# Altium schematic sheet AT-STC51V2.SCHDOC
size 300 x 200 mm
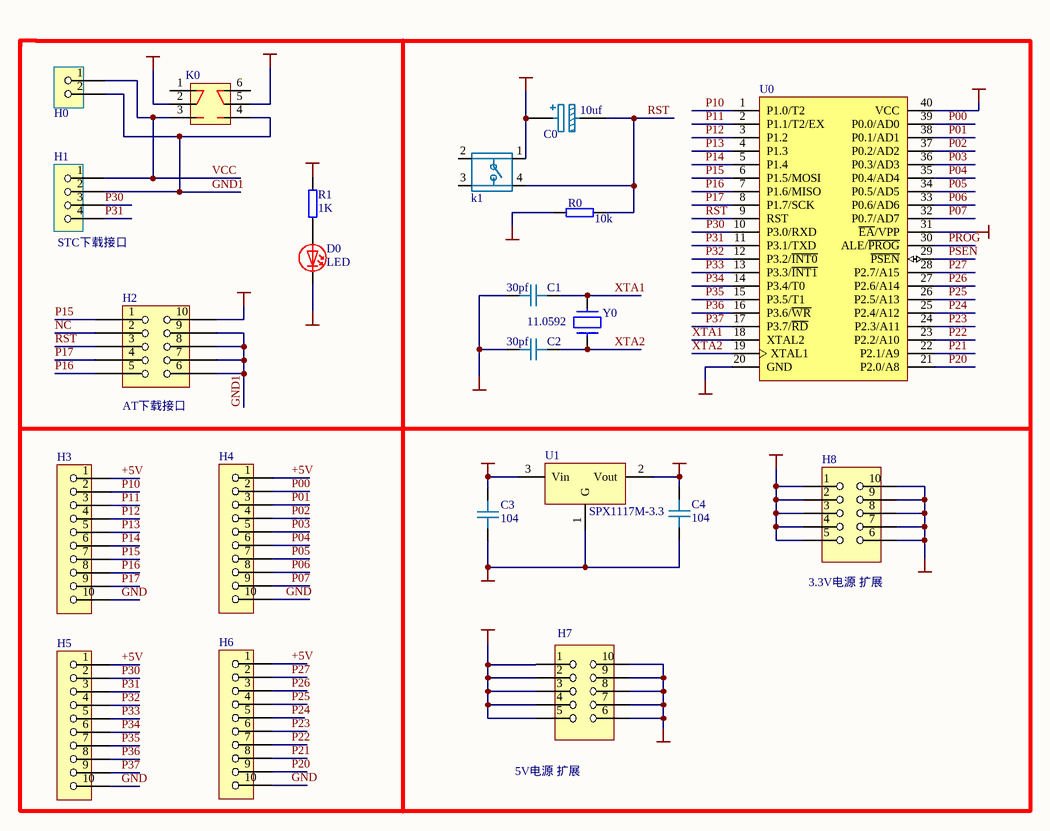
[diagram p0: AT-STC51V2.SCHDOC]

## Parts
C0  10uf  [Capacitor]
C1  30pf  [0805]
C2  30pf  [0805]
C3  104  [0805]
C4  104  [0805]
D0  LED  [LED-3]
H0  DIS2  [DIS2]  (value not drawn)
H1  DIS4  [dis4]  (value not drawn)
H2  PIN10  [DIS5*2-1]  (value not drawn)
H3  DIS10  [DIS10]  (value not drawn)
H4  DIS10  [DIS10]  (value not drawn)
H5  DIS10  [DIS10]  (value not drawn)
H6  DIS10  [DIS10]  (value not drawn)
H7  DIS5*2  [DIS5*2]  (value not drawn)
H8  DIS5*2  [DIS5*2]  (value not drawn)
K0  KEY  [KEY2]  (value not drawn)
k1  BUTTON  [BUTTON]  (value not drawn)
R0  10k  [resistor-0.4]
R1  1K  [resistor-0.4]
U0  AT89S52  [at89s51B]  (value not drawn)
U1  SPX1117M-3.3  [SPX1117M-3.3]
Y0  11.0592  [xtal_1]

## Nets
+3.3V: C4.2 H8.1 H8.2 H8.3 H8.4 H8.5 U1.2(Vout)
+5V: C0.1 C3.2 H3.1 H4.1 H5.1 H6.1 H7.1 H7.2 H7.3 H7.4 H7.5 K0.2 k1.1 R1.2 U0.31(~{EA}/VPP) U0.40(VCC) U1.3(Vin)
GND: C1.1 C2.1 C3.1 C4.1 D0.2 H3.10 H4.10 H5.10 H6.10 H7.6 H7.7 H7.8 H7.9 H7.10 H8.6 H8.7 H8.8 H8.9 H8.10 K0.5 R0.1 U0.20(GND) U1.1(G)
VCC: H0.1 H1.1 H2.10 K0.3
GND1: H0.2 H1.2 H2.6 H2.7 H2.8 H2.9 K0.4
NC: H2.2
P00: H4.2 U0.39(P0.0/AD0)
P01: H4.3 U0.38(P0.1/AD1)
P02: H4.4 U0.37(P0.2/AD2)
P03: H4.5 U0.36(P0.3/AD3)
P04: H4.6 U0.35(P0.4/AD4)
P05: H4.7 U0.34(P0.5/AD5)
P06: H4.8 U0.33(P0.6/AD6)
P07: H4.9 U0.32(P0.7/AD7)
P10: H3.2 U0.1(P1.0/T2)
P11: H3.3 U0.2(P1.1/T2/EX)
P12: H3.4 U0.3(P1.2)
P13: H3.5 U0.4(P1.3)
P14: H3.6 U0.5(P1.4)
P15: H2.1 H3.7 U0.6(P1.5/MOSI)
P16: H2.5 H3.8 U0.7(P1.6/MISO)
P17: H2.4 H3.9 U0.8(P1.7/SCK)
P20: H6.9 U0.21(P2.0/A8)
P21: H6.8 U0.22(P2.1/A9)
P22: H6.7 U0.23(P2.2/A10)
P23: H6.6 U0.24(P2.3/A11)
P24: H6.5 U0.25(P2.4/A12)
P25: H6.4 U0.26(P2.5/A13)
P26: H6.3 U0.27(P2.6/A14)
P27: H6.2 U0.28(P2.7/A15)
P30: H1.3 H5.2 U0.10(P3.0/RXD)
P31: H1.4 H5.3 U0.11(P3.1/TXD)
P32: H5.4 U0.12(P3.2/~{INT0})
P33: H5.5 U0.13(P3.3/~{INT1})
P34: H5.6 U0.14(P3.4/T0)
P35: H5.7 U0.15(P3.5/T1)
P36: H5.8 U0.16(P3.6/~{WR})
P37: H5.9 U0.17(P3.7/~{RD})
PROG: U0.30(ALE/~{PROG})
PSEN: U0.29(~{PSEN})
RST: C0.2 H2.3 k1.4 R0.2 U0.9(RST)
XTA1: C1.2 U0.18(XTAL2) Y0.2
XTA2: C2.2 U0.19(XTAL1) Y0.1
NetD0_1: D0.1 R1.1

Not connected (* = marked no-connect by the designer): K0 1 6; k1 2 3

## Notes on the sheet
- (near H1) STC下载接口
- (near H2) AT下载接口
- (near H8) 3.3V电源 扩展
- (near H7) 5V电源 扩展

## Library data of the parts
C0 = C_2
C1-C4 = C_1
D0 = LED-RED
H2 = ISP——10
K0 = KEY_1
R0 R1 = RESIS
U0 = AT89S51/52
Y0 = XTAL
